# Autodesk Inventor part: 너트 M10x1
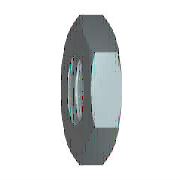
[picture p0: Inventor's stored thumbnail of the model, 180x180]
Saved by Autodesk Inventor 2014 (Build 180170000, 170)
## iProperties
Created: 2012-02
Part Number: 너트 M10x1
Material: 강철, 연강
Description: 6각 가는 너트 - 이중 모따기(부품 등급 A) - 정밀 나사산
Document SubType Name: Modeling
Standard: JIS B 1181
Designer: mduedu
Standards Organization: JIS
Language: ko-KR
Size Designation: M10x1
Categories: <MemberInstance><Categories><Category DisplayName="조임쇠" InternalName="e4da775c-781d-43d5-af7c-5136215cf5a6" Mnemonic="FSTN"><Category DisplayName="너트" InternalN
Density: 7.86 g/cm^3
Appearance: 강철
Mass: 6.13139 g
Surface Area: 6.99154 cm^2
Volume: 0.780075 cm^3
IsCustomPart: 1
Author: mduedu
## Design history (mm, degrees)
node "MSC_A1"
node "MSC_PT1"
node "MSC_PT2"
node "MSC_PF1"
body "Solid1"
sketch "스케치1"
  geometry: L1 (8, 4.619)-(8, -4.619); L2 (8, -4.619)-(0, -9.238); L3 (0, -9.238)-(-8, -4.619); L4 (-8, -4.619)-(-8, 4.619); L5 (-8, 4.619)-(0, 9.238); L6 (0, 9.238)-(8, 4.619); C1 r 8 at (0, 0); 2 further points
  constraints: 12 end point, 2 coincident, 1 centre point, 1 tangent, 1 vertical, 11 other
  dimensions: "d0" = 16 diameter of C1 (= ParS)
extrude "돌출1" new body sketch "스케치1" distance "d1" = 5 (= M); taper "d2" = 0 deg
sketch "스케치2"
  geometry: L1 (-8, 4.619)-(0, 9.238) reference; L2 (0, -9.238)-(-8, -4.619) reference; L3 (-8, 4.619)-(8, -4.619); L4 (-8, -4.619)-(8, 4.619); 1 further point
  constraints: 4 end point, 2 midpoint, 2 parallel
hole "구멍1" sketch "스케치2" diameter "d3" = 8.91747; stored, may be unused: countersink angle "d7" = 90 deg, drill point angle "d9" = 118 deg; dims "d4" = 6, "d5" = 4, "d6" = 2, "d8" = 8
chamfer "모따기1" distance "d10" = 0.5 (= 0.5 x PTC); stored, may be unused: second distance "d11" = 2, angle "d12" = 45 deg
revolve "회전1" stored, may be unused: angle "d15" = 90 deg
sketch "스케치3"
  geometry: L1 (-9.238, 5)-(-9.238, 4.285); L2 (-9.238, 4.285)-(-8, 5); L3 (-8, 5)-(-9.238, 5); L4 (-9.238, 0.715)-(-9.238, 0); L5 (-9.238, 0)-(-8, 0); L6 (-8, 0)-(-9.238, 0.715); L7 (0, 6)-(0, -1) reference; L8 (-4.619, 5)-(-9.238, 5) reference; L9 (-4.619, 0)-(-9.238, 0) reference; L10 (-9.238, 0)-(-9.238, 5) reference
  constraints: 12 end point, 4 collinear, 3 perpendicular, 2 equal length, 1 vertical
  dimensions: "d13" = 30 deg angle of L2 L3; "d14" = 8 distance from line of L2.end L7 (= 0.5 x ParS)
other parameters: "ParS" = 16 [user parameter; used in 2 equation terms], "M" = 5 [user parameter; used in 1 equation term], "PTC" = 1 [user parameter; used in 1 equation term], "d17" = 0, "d18" = 0, "d19" = 0, "d20" = 0, "d21" = 0, "d22" = 0, "d23" = 0
